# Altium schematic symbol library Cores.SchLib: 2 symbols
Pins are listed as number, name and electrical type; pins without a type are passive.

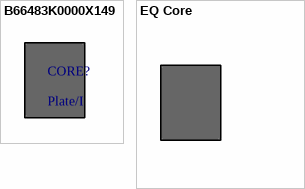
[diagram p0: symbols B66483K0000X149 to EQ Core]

## B66483K0000X149
designator CORE?, comment Plate/I
I core set, N49 material, gapped to 1.1uH /; Manufacturer: TDK; PartNumber: B66483K0000X149; Manufacturer Lifecycle Status: PRODUCTION; Description: Ferrite Cores, Planar Cores (Plate/I), Dimensions(A/B/C)=20/2

## EQ Core
designator CORE?, comment B66483G0000X149
EQ20 core set, N49 material, gapped to 1.1uH /; Manufacturer: TDK; CompType: Used in some BOM reports.  Useful for finding later.
footprint PCBComponent_1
